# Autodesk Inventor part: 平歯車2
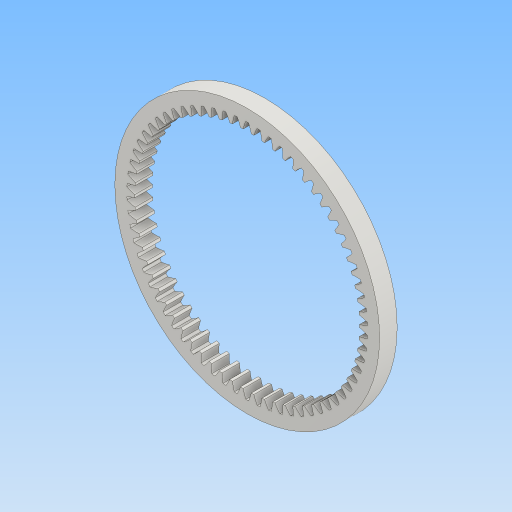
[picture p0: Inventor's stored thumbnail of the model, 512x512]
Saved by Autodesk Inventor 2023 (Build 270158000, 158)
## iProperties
CustomPartVersion: 1
Created: 2024-01
Part Number: 平歯車2
Material: Steel
Document SubType Name: Modeling
Designer: kumagai
Categories: <?xml version="1.0" encoding="UTF-16"?> <MemberInstance><Categories><FamilyTemplate><FamilyTemplateParameter ValueType="xs:double" Id="1" ObjectReferenceKey="da
Density: 1 g/cm^3
Appearance: Steel
Author: kumagai
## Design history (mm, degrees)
sketch "Sketch1"
  geometry: C1 r 37.675 at (0, 0)
  constraints: 1 centre point
  dimensions: "d0" = 75.35 diameter of C1 (= 1.1 x da_df)
extrude "Extrusion1" new body sketch "Sketch1" distance "d1" = 5 (= da_b); taper "d2" = 0 deg
workplane "Work Plane2"
sketch "Sketch2"
  geometry: C1 r 37.675 at (0, 0) reference; C2 r 33 at (0, 0)
  constraints: 1 centre point, 1 coincident
  dimensions: "d3" = 66 diameter of C2 (= da_d)
feature "ピッチ円直径" sketch "Sketch2" dims "d4" = 10, "d5" = 0
workplane "Work Plane8"
workplane "Work Plane9"
feature "平歯車" dims "da_b" = 5, "da_d" = 66, "da_z" = 660, "da_aw" = 21, "da_da" = 64, "da_df" = 68.5, "da_dw" = 66, "da_z2" = 220, "da_beta" = 0, "da_lefttooth" = 0, "da_righttooth" = 0, "da_straighttooth" = 10
body "Solid1"
body "Srf1"
other parameters: "d16" = 21 (= da_aw), "d17" = 0, "d34" = 0.476 (computed from da_z), "d39" = 0, "d45" = 0, "d47" = 21 (= da_aw), "d50" = 0, "d51" = 0, "d52" = 21 (= da_aw)
